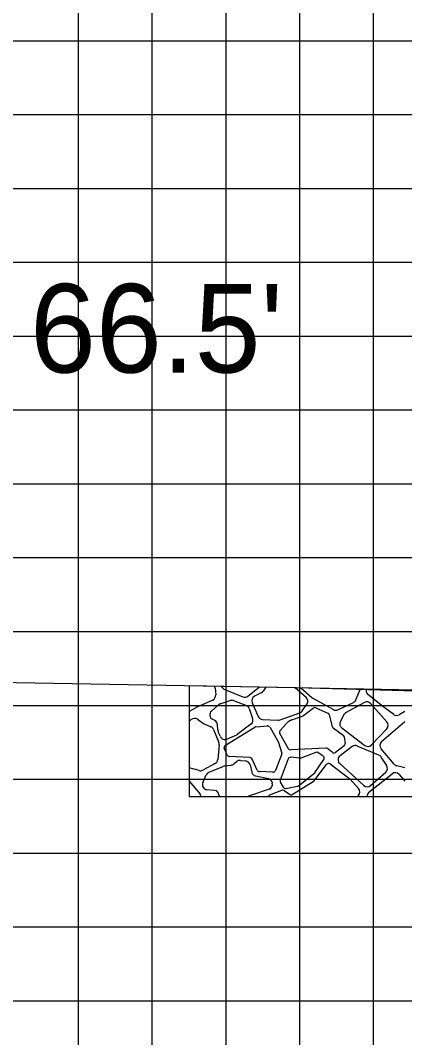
# Model space of a CAD drawing. Extents: x 1807045 to 1807388, y 442591 to 442811.
# Drawn here: x 1807141.97 to 1807147.18, y 442673.17 to 442686.94 of the extents above; entities that cross this region are included whole.
import ezdxf

# ---------------------------------------------------------------- set-up
doc = ezdxf.new("R2010")
doc.units = 0
for name, color, linetype in [('D_Roadway_SlopeLines', 7, 'Continuous'), ('D_Text_Standard', 7, 'Continuous'), ('MAJOR', 7, 'Continuous'), ('MINOR', 7, 'Continuous'), ('S_Roadway_Centerline', 7, 'Continuous')]:
    doc.layers.add(name, color=color, linetype=linetype)

msp = doc.modelspace()

# ---------------------------------------------------------------- linework, layer by layer
at = {"layer": 'D_Roadway_SlopeLines'}
for p, q in [((1807144.611, 442677.896), (1807144.619, 442677.805)), ((1807144.691, 442677.923), (1807144.719, 442677.894)), ((1807144.742, 442677.879), (1807144.986, 442677.779)), ((1807145.054, 442677.789), (1807145.209, 442677.913)), ((1807145.299, 442677.911), (1807145.263, 442677.858)), ((1807145.845, 442677.773), (1807145.695, 442677.904)), ((1807145.773, 442677.903), (1807145.922, 442677.769)), ((1807146.519, 442677.739), (1807146.583, 442677.887)), ((1807144.579, 442677.736), (1807144.355, 442677.637)), ((1807144.682, 442677.685), (1807144.815, 442677.73)), ((1807144.861, 442677.729), (1807145.035, 442677.662)), ((1807145.237, 442677.835), (1807145.145, 442677.789)), ((1807145.935, 442677.76), (1807146.214, 442677.607)), ((1807146.742, 442677.764), (1807146.682, 442677.812)), ((1807146.862, 442677.667), (1807146.743, 442677.764)), ((1807144.348, 442677.633), (1807144.261, 442677.582)), ((1807144.562, 442677.588), (1807144.658, 442677.672)), ((1807145.075, 442677.62), (1807145.12, 442677.486)), ((1807145.113, 442677.701), (1807145.195, 442677.515)), ((1807145.793, 442677.59), (1807145.857, 442677.684)), ((1807145.815, 442677.532), (1807145.942, 442677.627)), ((1807145.977, 442677.631), (1807146.139, 442677.559)), ((1807146.276, 442677.605), (1807146.485, 442677.705)), ((1807146.635, 442677.703), (1807146.38, 442677.563)), ((1807146.94, 442677.441), (1807146.718, 442677.688)), ((1807147.031, 442677.542), (1807146.865, 442677.665)), ((1807147.18, 442677.582), (1807147.106, 442677.538)), ((1807144.261, 442677.447), (1807144.289, 442677.472)), ((1807144.373, 442677.476), (1807144.452, 442677.421)), ((1807144.606, 442677.46), (1807144.576, 442677.476)), ((1807145.253, 442677.475), (1807145.465, 442677.463)), ((1807145.493, 442677.467), (1807145.76, 442677.564)), ((1807145.65, 442677.467), (1807145.769, 442677.508)), ((1807146.158, 442677.536), (1807146.197, 442677.38)), ((1807146.352, 442677.533), (1807146.308, 442677.444)), ((1807146.868, 442677.174), (1807147.18, 442677.447)), ((1807144.464, 442677.414), (1807144.553, 442677.375)), ((1807144.589, 442677.338), (1807144.662, 442677.16)), ((1807144.649, 442677.329), (1807144.642, 442677.406)), ((1807144.683, 442677.242), (1807144.654, 442677.308)), ((1807144.75, 442677.126), (1807145.148, 442677.371)), ((1807145.097, 442677.41), (1807144.912, 442677.27)), ((1807145.163, 442677.376), (1807145.319, 442677.388)), ((1807145.351, 442677.372), (1807145.462, 442677.182)), ((1807145.493, 442677.326), (1807145.58, 442677.421)), ((1807146.21, 442677.36), (1807146.345, 442677.261)), ((1807146.327, 442677.36), (1807146.639, 442677.122)), ((1807146.73, 442677.129), (1807146.938, 442677.348)), ((1807144.899, 442677.262), (1807144.773, 442677.207)), ((1807145.465, 442677.175), (1807145.514, 442677.017)), ((1807145.607, 442677.078), (1807145.488, 442677.285)), ((1807146.358, 442677.238), (1807146.372, 442677.15)), ((1807144.667, 442677.128), (1807144.649, 442676.932)), ((1807144.774, 442676.995), (1807144.736, 442677.084)), ((1807146.11, 442677.086), (1807145.638, 442677.061)), ((1807146.2, 442677.027), (1807146.132, 442677.079)), ((1807146.359, 442677.117), (1807146.241, 442677.027)), ((1807146.47, 442677.106), (1807146.304, 442676.983)), ((1807146.83, 442676.99), (1807146.537, 442677.114)), ((1807147.038, 442676.867), (1807146.861, 442677.078)), ((1807145.085, 442676.957), (1807144.803, 442676.974)), ((1807144.865, 442676.871), (1807144.903, 442676.903)), ((1807144.954, 442676.919), (1807145.027, 442676.912)), ((1807145.18, 442676.787), (1807145.114, 442676.937)), ((1807145.513, 442676.994), (1807145.428, 442676.782)), ((1807145.602, 442676.939), (1807145.493, 442676.654)), ((1807145.758, 442676.949), (1807145.637, 442676.961)), ((1807145.976, 442677.027), (1807145.773, 442676.951)), ((1807145.969, 442676.76), (1807146.083, 442676.931)), ((1807146.073, 442676.979), (1807146.006, 442677.023)), ((1807146.936, 442676.849), (1807146.861, 442676.964)), ((1807144.394, 442676.782), (1807144.261, 442676.817)), ((1807144.613, 442676.878), (1807144.443, 442676.787)), ((1807144.528, 442676.759), (1807144.72, 442676.839)), ((1807144.738, 442676.844), (1807144.829, 442676.855)), ((1807145.087, 442676.859), (1807145.108, 442676.762)), ((1807145.395, 442676.761), (1807145.21, 442676.767)), ((1807145.743, 442676.576), (1807145.962, 442676.753)), ((1807145.951, 442676.64), (1807146.122, 442676.865)), ((1807146.17, 442676.871), (1807146.436, 442676.668)), ((1807146.299, 442676.878), (1807146.627, 442676.581)), ((1807146.718, 442676.58), (1807146.923, 442676.76)), ((1807147.18, 442676.817), (1807147.073, 442676.845)), ((1807144.261, 442676.637), (1807144.407, 442676.46)), ((1807144.446, 442676.619), (1807144.492, 442676.723)), ((1807145.161, 442676.709), (1807145.331, 442676.674)), ((1807145.384, 442676.623), (1807145.386, 442676.612)), ((1807145.495, 442676.625), (1807145.535, 442676.557)), ((1807145.657, 442676.458), (1807145.942, 442676.632)), ((1807146.44, 442676.664), (1807146.556, 442676.539)), ((1807146.695, 442676.489), (1807147.01, 442676.739)), ((1807147.105, 442676.729), (1807147.18, 442676.637)), ((1807144.603, 442676.513), (1807144.501, 442676.523)), ((1807145.342, 442676.532), (1807145.076, 442676.438)), ((1807145.353, 442676.452), (1807145.515, 442676.515)), ((1807145.547, 442676.511), (1807145.619, 442676.46)), ((1807145.571, 442676.541), (1807145.727, 442676.569)), ((1807144.261, 442676.431), (1807159.166, 442676.431)), ((1807144.664, 442676.448), (1807144.664, 442676.453)), ((1807145.326, 442676.431), (1807145.343, 442676.446)), ((1807146.555, 442676.445), (1807146.541, 442676.431))]:
    msp.add_line(p, q, dxfattribs=at)
msp.add_lwpolyline([(1807166.273, 442681.484), (1807162.484, 442679.59), (1807158.627, 442677.662), (1807157.759, 442677.672), (1807144.261, 442677.931), (1807144.261, 442676.431)], dxfattribs=at)
for centre, major_axis, start_param, end_param in [((1807144.543, 442677.89), (0, 0.0683), 4.803049, 5.238884), ((1807144.768, 442677.943), (0, -0.0683), 5.497787, 5.893869), ((1807145.207, 442677.896), (0, -0.0683), 0.463648, 0.97362), ((1807146.725, 442677.866), (0, -0.0683), 4.41012, 5.608444), ((1807144.551, 442677.799), (0, 0.0683), 3.559817, 4.803049), ((1807144.837, 442677.665), (0, 0.0683), 5.917129, 6.604936), ((1807145.012, 442677.842), (0, -0.0683), 5.893869, 6.957926), ((1807145.176, 442677.728), (0, 0.0683), 0.463648, 1.985303), ((1807145.8, 442677.722), (0, -0.0683), 0.977446, 2.424153), ((1807145.968, 442677.82), (0, -0.0683), 5.554357, 5.782172), ((1807146.456, 442677.766), (0, -0.0683), 0.443382, 1.163165), ((1807146.668, 442677.643), (0, 0.0683), 5.44252, 6.785098), ((1807146.7, 442677.711), (0, 0.0683), 5.600869, 5.608444), ((1807144.383, 442677.575), (0, 0.0683), 0.418224, 0.534955), ((1807144.607, 442677.536), (0, -0.0683), 3.860423, 5.799738), ((1807144.703, 442677.62), (0, 0.0683), 0.321751, 0.71883), ((1807145.01, 442677.598), (0, 0.0683), 5.039487, 5.917129), ((1807145.737, 442677.628), (0, -0.0683), 0.347767, 0.977446), ((1807145.963, 442677.6), (0, 0.0342), 5.866747, 6.924845), ((1807146.247, 442677.667), (0, -0.0683), 5.782172, 6.726567), ((1807146.905, 442677.72), (0, -0.0683), 5.600869, 5.645637), ((1807144.334, 442677.42), (0, 0.0683), 5.668522, 7.003256), ((1807144.574, 442677.4), (0, 0.0683), 4.803049, 5.799738), ((1807145.056, 442677.464), (0, 0.0683), 3.787712, 5.039487), ((1807145.257, 442677.543), (0, -0.0683), 5.126896, 6.226907), ((1807145.469, 442677.531), (0, -0.0683), 6.226907, 6.630952), ((1807145.706, 442677.305), (0, 0.171), 0.333945, 0.825917), ((1807145.713, 442677.669), (0, -0.171), 0.333945, 0.641659), ((1807146.125, 442677.528), (0, 0.0342), 4.95256, 5.866747), ((1807146.369, 442677.414), (0, 0.0683), 1.108164, 2.48948), ((1807146.413, 442677.503), (0, 0.0683), 0.501913, 1.108164), ((1807146.889, 442677.395), (0, -0.0683), 0.810393, 2.300927), ((1807147.071, 442677.597), (0, -0.0683), 5.645637, 6.81814), ((1807144.491, 442677.476), (0, -0.0683), 5.668522, 5.870775), ((1807144.526, 442677.312), (0, 0.0683), 5.104729, 5.870775), ((1807144.717, 442677.336), (0, -0.0683), 4.803049, 5.120538), ((1807145.166, 442677.342), (0, 0.0342), 0.081452, 0.550676), ((1807145.321, 442677.354), (0, 0.0342), 5.244893, 6.364637), ((1807145.518, 442677.302), (0, -0.0342), 3.967509, 5.232357), ((1807146.23, 442677.388), (0, -0.0342), 4.95256, 5.649393), ((1807144.745, 442677.269), (0, -0.0683), 5.120538, 6.699624), ((1807144.871, 442677.325), (0, -0.0683), 0.416439, 0.646119), ((1807145.433, 442677.165), (0, 0.0342), 5.00783, 5.244893), ((1807146.325, 442677.233), (0, 0.0342), 4.865038, 5.649393), ((1807146.913, 442677.122), (0, -0.0683), 3.861663, 5.40978), ((1807144.599, 442677.134), (0, 0.0683), 4.621729, 5.104729), ((1807144.768, 442677.097), (0, -0.0342), 3.692268, 5.10718), ((1807145.636, 442677.095), (0, -0.0342), 5.232357, 6.335377), ((1807145.988, 442676.995), (0, 0.0342), 5.695183, 6.640689), ((1807146.112, 442677.052), (0, 0.0342), 5.62749, 6.335377), ((1807146.338, 442677.144), (0, 0.0342), 3.796699, 4.865038), ((1807146.511, 442677.052), (0, 0.0683), 5.881372, 6.922099), ((1807146.68, 442677.176), (0, -0.0683), 5.631073, 7.093578), ((1807144.581, 442676.939), (0, -0.0683), 0.489957, 1.480136), ((1807144.805, 442677.008), (0, -0.0342), 5.10718, 6.225111), ((1807144.947, 442676.851), (0, 0.0683), 6.183517, 6.987679), ((1807145.02, 442676.844), (0, 0.0683), 4.928939, 6.183517), ((1807145.083, 442676.923), (0, 0.0342), 5.126896, 6.225111), ((1807145.481, 442677.007), (0, 0.0342), 4.331883, 5.00783), ((1807145.634, 442676.927), (0, 0.0342), 6.185932, 7.487587), ((1807145.761, 442676.983), (0, -0.0342), 6.185932, 6.640689), ((1807146.054, 442676.95), (0, -0.0342), 0.982794, 2.55359), ((1807146.22, 442677.054), (0, -0.0342), 5.62749, 6.938291), ((1807146.345, 442676.928), (0, 0.0683), 0.638914, 2.406418), ((1807146.804, 442676.927), (0, 0.0683), 5.287694, 5.881372), ((1807144.411, 442676.848), (0, -0.0683), 6.025862, 6.773143), ((1807144.554, 442676.696), (0, 0.0683), 0.394791, 1.157466), ((1807144.747, 442676.776), (0, 0.0683), 0.124355, 0.394791), ((1807144.821, 442676.923), (0, -0.0683), 0.124355, 0.704494), ((1807145.174, 442676.776), (0, -0.0683), 4.928939, 6.08014), ((1807145.212, 442676.801), (0, -0.0342), 5.126896, 6.25041), ((1807145.396, 442676.795), (0, -0.0342), 6.25041, 7.473475), ((1807145.94, 442676.779), (0, -0.0342), 0.676737, 0.982794), ((1807146.149, 442676.844), (0, 0.0342), 5.630339, 7.201135), ((1807146.878, 442676.812), (0, -0.0683), 0.719883, 2.146101), ((1807147.052, 442676.685), (0, 0.0683), 5.401291, 6.952921), ((1807147.09, 442676.911), (0, -0.0683), 5.40978, 6.025862), ((1807144.508, 442676.591), (0, -0.0683), 4.299059, 6.17752), ((1807145.317, 442676.607), (0, 0.0683), 4.941621, 6.08014), ((1807145.525, 442676.642), (0, 0.0342), 1.204402, 2.105751), ((1807145.924, 442676.661), (0, -0.0342), 0.547562, 0.91795), ((1807146.415, 442676.64), (0, 0.0342), 5.459199, 5.630339), ((1807144.596, 442676.445), (0, 0.0683), 4.831818, 6.17752), ((1807145.32, 442676.596), (0, 0.0683), 3.480291, 4.941621), ((1807145.527, 442676.483), (0, 0.0342), 5.662936, 6.653091), ((1807145.565, 442676.575), (0, -0.0342), 5.247344, 6.461278), ((1807145.721, 442676.603), (0, -0.0342), 0.178093, 0.676737), ((1807146.506, 442676.492), (0, 0.0683), 3.950796, 5.459199), ((1807146.673, 442676.631), (0, -0.0683), 5.54801, 7.003068), ((1807146.737, 442676.436), (0, -0.0683), 3.811328, 4.781061), ((1807144.354, 442676.417), (0, 0.0683), 4.923619, 5.401291), ((1807144.732, 442676.456), (0, -0.0683), 4.831818, 5.090955), ((1807145.098, 442676.373), (0, 0.0683), 0.338698, 0.568262), ((1807145.366, 442676.421), (0, 0.0342), 0.369906, 0.736656), ((1807145.639, 442676.487), (0, -0.0342), 5.662936, 6.830748)]:
    msp.add_ellipse(centre, major_axis=major_axis, ratio=0.99895, start_param=start_param, end_param=end_param, dxfattribs=at)
at = {"layer": 'MAJOR'}
for p, q in [((1807070.759, 442683.665), (1807350.759, 442683.665)), ((1807070.759, 442678.665), (1807350.759, 442678.665)), ((1807070.759, 442673.665), (1807350.759, 442673.665))]:
    msp.add_line(p, q, dxfattribs=at)
at = {"layer": 'MINOR'}
for p, q in [((1807142.759, 442663.665), (1807142.759, 442698.665)), ((1807143.759, 442663.665), (1807143.759, 442698.665)), ((1807144.759, 442663.665), (1807144.759, 442698.665)), ((1807145.759, 442663.665), (1807145.759, 442698.665)), ((1807146.759, 442663.665), (1807146.759, 442698.665)), ((1807070.759, 442686.665), (1807350.759, 442686.665)), ((1807070.759, 442685.665), (1807350.759, 442685.665)), ((1807070.759, 442684.665), (1807350.759, 442684.665)), ((1807070.759, 442682.665), (1807350.759, 442682.665)), ((1807070.759, 442681.665), (1807350.759, 442681.665)), ((1807070.759, 442680.665), (1807350.759, 442680.665)), ((1807070.759, 442679.665), (1807350.759, 442679.665)), ((1807070.759, 442677.665), (1807350.759, 442677.665)), ((1807070.759, 442676.665), (1807350.759, 442676.665)), ((1807070.759, 442675.665), (1807350.759, 442675.665)), ((1807070.759, 442674.665), (1807350.759, 442674.665))]:
    msp.add_line(p, q, dxfattribs=at)
at = {"layer": 'S_Roadway_Centerline'}
msp.add_lwpolyline([(1807137.321, 442678.055), (1807145.714, 442677.905), (1807153.421, 442677.695), (1807163.888, 442677.64), (1807167.09, 442677.522), (1807176.514, 442677.036), (1807189.139, 442676.626), (1807189.4, 442676.62), (1807189.676, 442676.614), (1807203.419, 442676.739), (1807210.876, 442676.624), (1807214.273, 442676.566), (1807222.824, 442676.92), (1807231.138, 442676.312), (1807247.162, 442676.483), (1807251.677, 442676.55), (1807259.938, 442676.383), (1807289.258, 442676.117)], dxfattribs=at)

# ---------------------------------------------------------------- texts
at = {"layer": 'D_Text_Standard'}
msp.add_text("66.5'", height=1.2, dxfattribs=at).set_placement((1807142.104, 442682.171))

doc.saveas('drawing.dxf')
